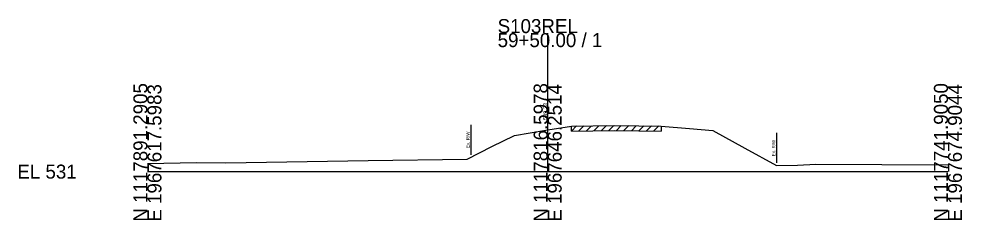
# Model space of a CAD drawing. Extents: x -26 to 163, y -10 to 24518.
# Drawn here: x -25.7 to 162.8, y 10490.3 to 10530.5 of the extents above; entities that cross this region are included whole.
import ezdxf

# ---------------------------------------------------------------- set-up
doc = ezdxf.new("R2010")
doc.units = 0
for name, color, linetype in [('RD_GPK_XS_Cell', 7, 'Continuous'), ('RD_XS_ExGround', 7, 'Continuous'), ('RD_XS_ExPaveRet', 7, 'Continuous'), ('RD_XS_ExRW', 7, 'Continuous'), ('RD_XS_TX_Elev_EX', 7, 'Continuous')]:
    doc.layers.add(name, color=color, linetype=linetype)

msp = doc.modelspace()

# ---------------------------------------------------------------- linework, layer by layer
at = {"layer": 'RD_GPK_XS_Cell'}
for p, q in [((80, 10500), (80, 10527.68)), ((0, 10500), (80, 10500)), ((80, 10500), (160, 10500))]:
    msp.add_line(p, q, dxfattribs=at)
at = {"layer": 'RD_XS_ExGround'}
msp.add_lwpolyline([(0, 10501.61), (9.79, 10501.82), (15.65, 10501.78), (44.14, 10502.25), (63.9, 10502.51), (68.85, 10504.99), (73.34, 10507.22), (79.61, 10508.27), (80, 10508.33), (84.73, 10509.1), (89, 10509.16), (93.32, 10509.23), (98.19, 10509.16), (102.66, 10509.11), (108.32, 10508.59), (113.02, 10508.2), (119.43, 10504.68), (125.74, 10501.23), (129.94, 10501.31), (133.57, 10501.49), (160, 10501.33)], dxfattribs=at)
at = {"layer": 'RD_XS_ExPaveRet'}
for p, q in [((84.73, 10508.1), (85.75, 10509.12)), ((84.73, 10508.1), (84.73, 10509.1)), ((86.23, 10508.12), (87.25, 10509.14)), ((87.73, 10508.15), (88.75, 10509.16)), ((89.23, 10508.17), (90.25, 10509.18)), ((90.73, 10508.19), (91.75, 10509.2)), ((92.23, 10508.21), (93.25, 10509.23)), ((93.74, 10508.22), (94.72, 10509.21)), ((95.24, 10508.2), (96.22, 10509.19)), ((96.74, 10508.18), (97.72, 10509.17)), ((98.24, 10508.16), (99.23, 10509.15)), ((99.74, 10508.14), (100.73, 10509.13)), ((101.24, 10508.13), (102.23, 10509.12)), ((102.66, 10509.11), (102.66, 10508.11)), ((84.73, 10508.1), (89, 10508.16)), ((89, 10508.16), (93.32, 10508.23)), ((93.32, 10508.23), (98.19, 10508.16)), ((98.19, 10508.16), (102.66, 10508.11))]:
    msp.add_line(p, q, dxfattribs=at)
at = {"layer": 'RD_XS_ExRW'}
for p, q in [((64.63, 10509.38), (64.63, 10503.38)), ((125.74, 10507.73), (125.74, 10501.73))]:
    msp.add_line(p, q, dxfattribs=at)

# ---------------------------------------------------------------- texts
at = {"layer": 'RD_GPK_XS_Cell'}
for s, p in [('S103REL', (70, 10527.68)), ('59+50.00 / 1', (70, 10524.88)), ('EL 531', (-26, 10498.6))]:
    msp.add_text(s, height=2.8, dxfattribs=at).set_placement(p)
for s, p in [('N 1117891.2905', (0, 10490)), ('E 1967617.5983', (2.8, 10490)), ('N 1117816.5978', (80, 10490)), ('E 1967646.2514', (82.8, 10490)), ('N 1117741.9050', (160, 10490)), ('E 1967674.9044', (162.8, 10490))]:
    msp.add_text(s, height=2.8, rotation=90, dxfattribs=at).set_placement(p)
at = {"layer": 'RD_XS_ExRW'}
for p in [(64.38, 10504.72), (125.49, 10503.07)]:
    msp.add_text('Ex. R/W ', height=0.65, rotation=90, dxfattribs=at).set_placement(p)
at = {"layer": 'RD_XS_TX_Elev_EX'}
msp.add_text('539.33', height=0.8, rotation=90, dxfattribs=at).set_placement((79.9, 10510.33))

doc.saveas('drawing.dxf')
